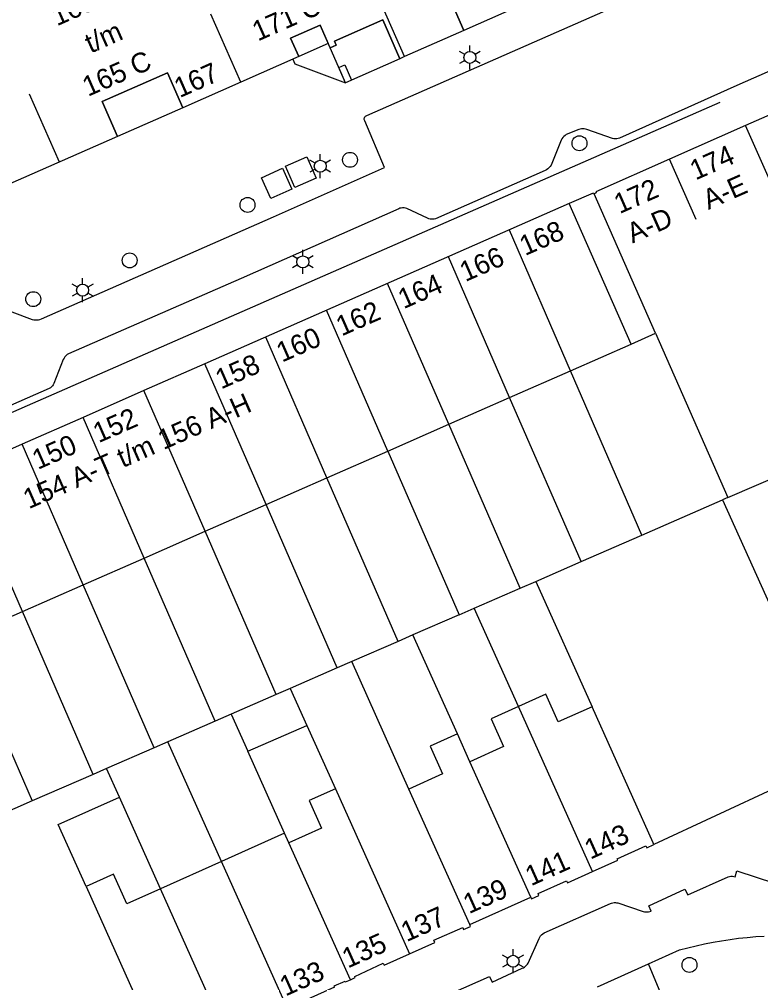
# Model space of a CAD drawing. Extents: x 122462 to 123306, y 485548 to 486417.
# Drawn here: x 123114.5 to 123170.2, y 485591 to 485663.3 of the extents above; entities that cross this region are included whole.
import ezdxf

# ---------------------------------------------------------------- set-up
doc = ezdxf.new("R2010")
doc.units = 0
for name, color, linetype in [('Level 1', 7, 'Continuous'), ('Level 10', 7, 'Continuous'), ('Level 11', 7, 'Continuous'), ('Level 17', 7, 'Continuous'), ('Level 19', 7, 'Continuous'), ('Level 34', 7, 'Continuous'), ('Level 4', 7, 'Continuous'), ('Level 42', 7, 'Continuous'), ('Level 5', 7, 'Continuous'), ('Level 50', 7, 'Continuous'), ('Level 53', 7, 'Continuous'), ('Level 58', 7, 'Continuous')]:
    doc.layers.add(name, color=color, linetype=linetype)

msp = doc.modelspace()

# ---------------------------------------------------------------- linework, layer by layer
at = {"layer": 'Level 1'}
for p, q in [((123174.718, 485657.832), (123169.02, 485655.311)), ((123169.02, 485655.311), (123163.323, 485652.791)), ((123155.8, 485649.462), (123128.458, 485637.443)), ((123160.431, 485638.928), (123162.261, 485639.734)), ((123162.261, 485639.734), (123167.681, 485627.406)), ((123155.89, 485636.928), (123160.431, 485638.928)), ((123128.458, 485637.443), (123123.89, 485635.435)), ((123167.681, 485627.406), (123190.52, 485637.283)), ((123151.323, 485634.917), (123155.89, 485636.928)), ((123123.89, 485635.435), (123119.322, 485633.427)), ((123146.755, 485632.909), (123151.323, 485634.917)), ((123119.322, 485633.427), (123114.754, 485631.419)), ((123142.186, 485630.902), (123146.755, 485632.909)), ((123114.754, 485631.419), (123110.186, 485629.41)), ((123137.617, 485628.895), (123142.186, 485630.902)), ((123133.049, 485626.888), (123137.617, 485628.895)), ((123128.48, 485624.881), (123133.049, 485626.888)), ((123123.911, 485622.874), (123128.48, 485624.881)), ((123119.342, 485620.868), (123123.911, 485622.874)), ((123114.774, 485618.861), (123119.342, 485620.868)), ((123110.205, 485616.854), (123114.774, 485618.861)), ((123139.476, 485615.107), (123138.38, 485614.629)), ((123143.769, 485605.548), (123139.476, 485615.107)), ((123138.38, 485614.629), (123134.869, 485613.097)), ((123133.806, 485612.633), (123130.43, 485611.161)), ((123134.869, 485613.097), (123133.806, 485612.633)), ((123130.43, 485611.161), (123131.675, 485608.39)), ((123131.675, 485608.39), (123136.115, 485610.326)), ((123136.115, 485610.326), (123138.253, 485605.568)), ((123148.342, 485607.602), (123147.408, 485609.68)), ((123121.09, 485607.089), (123120.084, 485606.65)), ((123122.054, 485604.942), (123121.09, 485607.089)), ((123120.084, 485606.65), (123115.51, 485604.655)), ((123115.51, 485604.655), (123110.937, 485602.659)), ((123134.434, 485602.248), (123129.7, 485600.122)), ((123134.768, 485601.504), (123134.434, 485602.248)), ((123129.7, 485600.122), (123125.14, 485598.073)), ((123148.33, 485595.39), (123152.91, 485597.429))]:
    msp.add_line(p, q, dxfattribs=at)
for points in [[(123149.476, 485664.843), (123147.26, 485663.865), (123147.886, 485662.447), (123143.438, 485660.484)], [(123143.438, 485660.484), (123143.083, 485660.327), (123141.803, 485663.235), (123138.179, 485661.639), (123138.304, 485661.356), (123137.855, 485661.158), (123137.108, 485662.854), (123134.89, 485661.877), (123135.503, 485660.486), (123126.802, 485656.654), (123125.651, 485659.27), (123120.75, 485657.111), (123121.902, 485654.496), (123113.193, 485650.66), (123112.58, 485652.052), (123110.428, 485651.104), (123111.173, 485649.408), (123110.724, 485649.211), (123110.6, 485649.494), (123106.975, 485647.9), (123108.257, 485644.987), (123107.851, 485644.807)], [(123163.323, 485652.791), (123157.782, 485650.339), (123157.812, 485650.27), (123157.659, 485650.203)], [(123157.659, 485650.203), (123157.61, 485650.182), (123157.582, 485650.246), (123155.8, 485649.462)], [(123157.502, 485611.716), (123154.973, 485610.581), (123154.04, 485612.659), (123151.987, 485611.737)], [(123151.987, 485611.737), (123149.936, 485610.815), (123150.869, 485608.737), (123148.342, 485607.602)], [(123162.141, 485601.391), (123162.08, 485601.519), (123157.502, 485611.716)], [(123147.408, 485609.68), (123145.356, 485608.758), (123146.29, 485606.68), (123143.769, 485605.548)], [(123138.253, 485605.568), (123136.286, 485604.684), (123137.22, 485602.605), (123134.768, 485601.504)], [(123119.545, 485598.239), (123117.461, 485602.879), (123122.054, 485604.942)], [(123157.546, 485599.361), (123159.441, 485600.211), (123159.391, 485600.321), (123161.541, 485601.301), (123161.611, 485601.151), (123162.141, 485601.391)], [(123125.14, 485598.073), (123122.599, 485596.932), (123121.598, 485599.161), (123119.545, 485598.239)], [(123152.91, 485597.429), (123152.961, 485597.311), (123153.511, 485597.571), (123153.451, 485597.711), (123155.581, 485598.661), (123155.651, 485598.511), (123157.546, 485599.361)], [(123143.811, 485593.196), (123145.701, 485594.051), (123145.631, 485594.211), (123147.801, 485595.171), (123147.871, 485595.011), (123148.395, 485595.244), (123148.33, 485595.39)], [(123139.376, 485591.246), (123139.741, 485591.411), (123139.701, 485591.501), (123141.841, 485592.491), (123141.921, 485592.341), (123143.811, 485593.196)], [(123134.641, 485589.121), (123134.841, 485589.211), (123134.811, 485589.281), (123135.621, 485589.651), (123135.651, 485589.571), (123138.201, 485590.721), (123138.171, 485590.791), (123138.981, 485591.151), (123139.011, 485591.081), (123139.376, 485591.246)]]:
    msp.add_lwpolyline(points, dxfattribs=at)
at = {"layer": 'Level 10'}
for points in [[(123147.886, 485662.447), (123147.26, 485663.865), (123149.476, 485664.843), (123152.186, 485666.039), (123152.811, 485664.619), (123147.886, 485662.447)], [(123139.009, 485658.529), (123137.855, 485661.158), (123138.304, 485661.356), (123138.179, 485661.639), (123141.803, 485663.235), (123143.083, 485660.327), (123139.009, 485658.529)], [(123135.503, 485660.486), (123134.89, 485661.877), (123137.108, 485662.854), (123137.721, 485661.463), (123135.503, 485660.486)], [(123121.902, 485654.496), (123120.75, 485657.111), (123125.651, 485659.27), (123126.802, 485656.654), (123121.902, 485654.496)]]:
    msp.add_lwpolyline(points, dxfattribs=at)
at = {"layer": 'Level 11'}
msp.add_lwpolyline([(123135.059, 485660.289), (123135.214, 485659.944), (123139.009, 485658.529)], dxfattribs=at)
at = {"layer": 'Level 17'}
for p, q in [((123167.101, 485657.051), (123068.183, 485613.738)), ((123157.907, 485590.72), (123161.74, 485592.438))]:
    msp.add_line(p, q, dxfattribs=at)
for points in [[(123110.693, 485642.568), (123115.505, 485640.78), (123115.621, 485640.752), (123115.739, 485640.737), (123115.858, 485640.737), (123115.976, 485640.751), (123116.092, 485640.779), (123116.204, 485640.82), (123133.619, 485648.481), (123141.937, 485652.18), (123140.466, 485655.661), (123140.436, 485655.717), (123140.421, 485655.779), (123140.421, 485655.842), (123140.435, 485655.904), (123140.464, 485655.961), (123140.505, 485656.009), (123140.556, 485656.047), (123140.615, 485656.071), (123204.708, 485684.255)], [(123207.552, 485675.569), (123168.357, 485658.322), (123159.567, 485654.37), (123159.462, 485654.338), (123159.355, 485654.319), (123159.245, 485654.311), (123159.136, 485654.317), (123159.028, 485654.334), (123157.116, 485655.015), (123157.019, 485655.045), (123156.92, 485655.064), (123156.819, 485655.071), (123156.717, 485655.068), (123156.617, 485655.053), (123156.519, 485655.027), (123155.575, 485654.649), (123155.48, 485654.579), (123155.393, 485654.499), (123155.315, 485654.41), (123155.247, 485654.313), (123155.19, 485654.209), (123154.43, 485652.356), (123154.362, 485652.254), (123154.283, 485652.16), (123154.193, 485652.076), (123154.094, 485652.003), (123153.987, 485651.942), (123145.75, 485648.323), (123145.654, 485648.297), (123145.556, 485648.283), (123145.457, 485648.283), (123145.359, 485648.295), (123145.263, 485648.32), (123145.171, 485648.358), (123143.6, 485649.089), (123143.502, 485649.12), (123143.4, 485649.138), (123143.297, 485649.142), (123143.195, 485649.132), (123143.094, 485649.109), (123142.998, 485649.072), (123131.181, 485643.853), (123118.233, 485638.197), (123118.133, 485638.132), (123118.042, 485638.054), (123117.962, 485637.965), (123117.895, 485637.866), (123117.841, 485637.759), (123117.127, 485635.968), (123117.083, 485635.875), (123117.025, 485635.79), (123116.955, 485635.714), (123116.875, 485635.649), (123116.786, 485635.597), (123108.895, 485632.144)], [(123175.966, 485607.987), (123176.029, 485607.84), (123162.141, 485601.391)], [(123147.048, 485590.265), (123149.812, 485591.479), (123150.001, 485591.064), (123152.26, 485592.113), (123152.351, 485592.151), (123152.438, 485592.201), (123152.517, 485592.261), (123152.588, 485592.33), (123152.651, 485592.407), (123152.703, 485592.491), (123153.525, 485594.333), (123153.578, 485594.437), (123153.643, 485594.533), (123153.721, 485594.62), (123153.809, 485594.696), (123153.907, 485594.759), (123158.883, 485596.955), (123158.971, 485596.992), (123159.063, 485597.018), (123159.158, 485597.032), (123159.253, 485597.035), (123159.349, 485597.026), (123159.442, 485597.005), (123161.344, 485596.374), (123161.442, 485596.348), (123161.542, 485596.333), (123161.643, 485596.331), (123161.744, 485596.341), (123161.843, 485596.363), (123161.938, 485596.397), (123161.752, 485596.795), (123164.474, 485598.048), (123164.69, 485597.618), (123167.72, 485598.953), (123167.821, 485598.984), (123167.926, 485599.003), (123168.032, 485599.007), (123168.137, 485598.997), (123168.241, 485598.974), (123168.353, 485599.407), (123171.199, 485598.496)], [(123161.74, 485592.438), (123164.067, 485593.481), (123164.691, 485593.647), (123165.318, 485593.8), (123165.948, 485593.938), (123166.581, 485594.063), (123167.217, 485594.174), (123167.855, 485594.271), (123168.495, 485594.354), (123169.137, 485594.423), (123169.78, 485594.478), (123170.424, 485594.519)], [(123164.224, 485585.952), (123163.282, 485588.094), (123163.044, 485589.305), (123161.74, 485592.438)]]:
    msp.add_lwpolyline(points, dxfattribs=at)
at = {"layer": 'Level 19'}
for p, q in [((123161.25, 485624.601), (123155.89, 485636.928)), ((123156.676, 485622.607), (123151.323, 485634.917)), ((123152.102, 485620.613), (123146.755, 485632.909)), ((123142.186, 485630.902), (123147.528, 485618.618)), ((123142.954, 485616.623), (123137.617, 485628.895)), ((123161.25, 485624.601), (123167.285, 485627.233)), ((123167.681, 485627.406), (123167.285, 485627.233)), ((123167.285, 485627.233), (123172.975, 485614.616)), ((123138.38, 485614.629), (123133.049, 485626.888)), ((123133.806, 485612.633), (123128.48, 485624.881)), ((123156.676, 485622.607), (123161.25, 485624.601)), ((123129.232, 485610.639), (123123.911, 485622.874)), ((123153.277, 485621.125), (123156.676, 485622.607)), ((123124.658, 485608.645), (123119.342, 485620.868)), ((123148.673, 485619.117), (123152.102, 485620.613)), ((123152.102, 485620.613), (123153.277, 485621.125)), ((123153.277, 485621.125), (123157.502, 485611.716)), ((123147.528, 485618.618), (123148.673, 485619.117)), ((123151.987, 485611.737), (123148.673, 485619.117)), ((123120.084, 485606.65), (123114.774, 485618.861)), ((123147.528, 485618.618), (123144.072, 485617.111)), ((123144.072, 485617.111), (123142.954, 485616.623)), ((123147.408, 485609.68), (123144.072, 485617.111)), ((123110.205, 485616.854), (123115.51, 485604.655)), ((123142.954, 485616.623), (123139.476, 485615.107)), ((123130.43, 485611.161), (123129.232, 485610.639)), ((123129.232, 485610.639), (123125.674, 485609.088)), ((123125.674, 485609.088), (123124.658, 485608.645)), ((123129.7, 485600.122), (123125.674, 485609.088)), ((123124.658, 485608.645), (123121.09, 485607.089)), ((123134.434, 485602.248), (123131.675, 485608.39)), ((123125.14, 485598.073), (123122.054, 485604.942))]:
    msp.add_line(p, q, dxfattribs=at)
at = {"layer": 'Level 34'}
msp.add_lwpolyline([(123139.009, 485658.529), (123138.511, 485659.667), (123138.959, 485659.864), (123139.46, 485658.729), (123139.009, 485658.529)], dxfattribs=at)
at = {"layer": 'Level 4'}
for p, q in [((123143.438, 485660.484), (123138.094, 485672.594)), ((123162.261, 485639.734), (123157.659, 485650.203)), ((123134.869, 485613.097), (123136.115, 485610.326)), ((123157.546, 485599.361), (123151.987, 485611.737)), ((123152.91, 485597.429), (123148.342, 485607.602)), ((123138.253, 485605.568), (123143.811, 485593.196)), ((123148.33, 485595.39), (123143.769, 485605.548)), ((123139.376, 485591.246), (123134.768, 485601.504)), ((123134.641, 485589.121), (123129.7, 485600.122)), ((123130.049, 485587.14), (123125.14, 485598.073))]:
    msp.add_line(p, q, dxfattribs=at)
at = {"layer": 'Level 42'}
for points in [[(123135.217, 485650.678), (123134.515, 485652.261), (123136.098, 485652.963), (123136.8, 485651.38), (123135.217, 485650.678)], [(123133.421, 485649.835), (123132.711, 485651.404), (123134.28, 485652.114), (123134.99, 485650.545), (123133.421, 485649.835)]]:
    msp.add_lwpolyline(points, dxfattribs=at)
at = {"layer": 'Level 5'}
for p, q in [((123131.152, 485658.57), (123128.911, 485663.66)), ((123117.547, 485652.578), (123115.306, 485657.667)), ((123174.344, 485643.279), (123169.02, 485655.311)), ((123165.324, 485648.27), (123163.323, 485652.791)), ((123160.431, 485638.928), (123155.8, 485649.462)), ((123155.89, 485636.928), (123151.3, 485647.481)), ((123151.323, 485634.917), (123146.733, 485645.472)), ((123146.755, 485632.909), (123142.164, 485643.464)), ((123142.186, 485630.902), (123137.596, 485641.457)), ((123137.617, 485628.895), (123133.027, 485639.45)), ((123133.049, 485626.888), (123128.458, 485637.443)), ((123123.89, 485635.435), (123123.889, 485635.436)), ((123128.48, 485624.881), (123123.89, 485635.435)), ((123119.322, 485633.427), (123119.321, 485633.429)), ((123123.911, 485622.874), (123119.322, 485633.427)), ((123114.754, 485631.419), (123114.752, 485631.423)), ((123119.342, 485620.868), (123114.754, 485631.419)), ((123114.774, 485618.861), (123110.186, 485629.41)), ((123119.545, 485598.239), (123125.439, 485585.11))]:
    msp.add_line(p, q, dxfattribs=at)
at = {"layer": 'Level 50'}
for p, q in [((123148.34, 485660.879), (123148.34, 485661.329)), ((123147.95, 485660.654), (123147.56, 485660.879)), ((123149.119, 485660.879), (123148.729, 485660.654)), ((123147.95, 485660.204), (123147.56, 485659.979)), ((123148.34, 485659.529), (123148.34, 485659.979)), ((123149.119, 485659.979), (123148.729, 485660.204)), ((123137.118, 485652.716), (123137.118, 485653.166)), ((123136.728, 485652.491), (123136.338, 485652.716)), ((123137.897, 485652.716), (123137.507, 485652.491)), ((123136.728, 485652.041), (123136.338, 485651.816)), ((123137.118, 485651.366), (123137.118, 485651.816)), ((123137.897, 485651.816), (123137.507, 485652.041)), ((123135.809, 485645.542), (123135.809, 485645.992)), ((123135.419, 485645.317), (123135.029, 485645.542)), ((123136.588, 485645.542), (123136.198, 485645.317)), ((123135.419, 485644.867), (123135.029, 485644.642)), ((123135.809, 485644.192), (123135.809, 485644.642)), ((123136.588, 485644.642), (123136.198, 485644.867)), ((123119.29, 485643.419), (123119.29, 485643.869)), ((123118.9, 485643.194), (123118.51, 485643.419)), ((123120.069, 485643.419), (123119.679, 485643.194)), ((123118.9, 485642.744), (123118.51, 485642.519)), ((123119.29, 485642.069), (123119.29, 485642.519)), ((123120.069, 485642.519), (123119.679, 485642.744)), ((123151.187, 485592.855), (123150.797, 485593.08)), ((123151.577, 485593.08), (123151.577, 485593.53)), ((123152.356, 485593.08), (123151.966, 485592.855)), ((123151.187, 485592.405), (123150.797, 485592.18)), ((123152.356, 485592.18), (123151.966, 485592.405)), ((123151.577, 485591.73), (123151.577, 485592.18))]:
    msp.add_line(p, q, dxfattribs=at)
for centre in [(123148.34, 485660.429), (123137.118, 485652.266), (123135.809, 485645.092), (123119.29, 485642.969), (123151.577, 485592.63)]:
    msp.add_circle(centre, 0.45, dxfattribs=at)
at = {"layer": 'Level 53'}
for centre in [(123156.562, 485653.987), (123139.348, 485652.745), (123131.659, 485649.364), (123122.82, 485645.199), (123115.584, 485642.296), (123164.813, 485592.357)]:
    msp.add_circle(centre, 0.56, dxfattribs=at)

# ---------------------------------------------------------------- texts
at = {"layer": 'Level 58'}
for s, rotation, p in [('163 A', 23.78372, (123117.364, 485662.756)), ('171 C', 23.77023, (123132.435, 485661.617)), ('t/m', 23.78372, (123119.891, 485660.712)), ('165 C', 23.78372, (123119.695, 485657.467)), ('167', 23.77862, (123126.577, 485657.374)), ('174', 23.86721, (123165.27, 485651.193)), ('A-E', 23.86721, (123166.236, 485648.984)), ('172', 23.86721, (123159.574, 485648.671)), ('A-D', 23.86721, (123160.539, 485646.464)), ('168', 23.77376, (123152.482, 485645.524)), ('166', 23.76731, (123147.999, 485643.572)), ('164', 23.74425, (123143.371, 485641.536)), ('162', 23.70786, (123138.721, 485639.495)), ('160', 23.71538, (123134.249, 485637.53)), ('158', 23.72666, (123129.674, 485635.515)), ('154 A-T t/m 156 A-H', 23.71418, (123115.251, 485626.531)), ('152', 23.71473, (123120.49, 485631.486)), ('150', 23.71473, (123115.927, 485629.481)), ('143', 24.17885, (123157.372, 485600.245)), ('141', 24.17885, (123152.926, 485598.249)), ('139', 24.17885, (123148.269, 485596.158)), ('137', 24.17885, (123143.596, 485594.06)), ('135', 24.17885, (123139.186, 485592.08)), ('133', 24.17885, (123134.51, 485589.98))]:
    msp.add_text(s, height=1.5, rotation=rotation, dxfattribs=at).set_placement(p)

doc.saveas('drawing.dxf')
